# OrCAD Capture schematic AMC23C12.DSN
size A
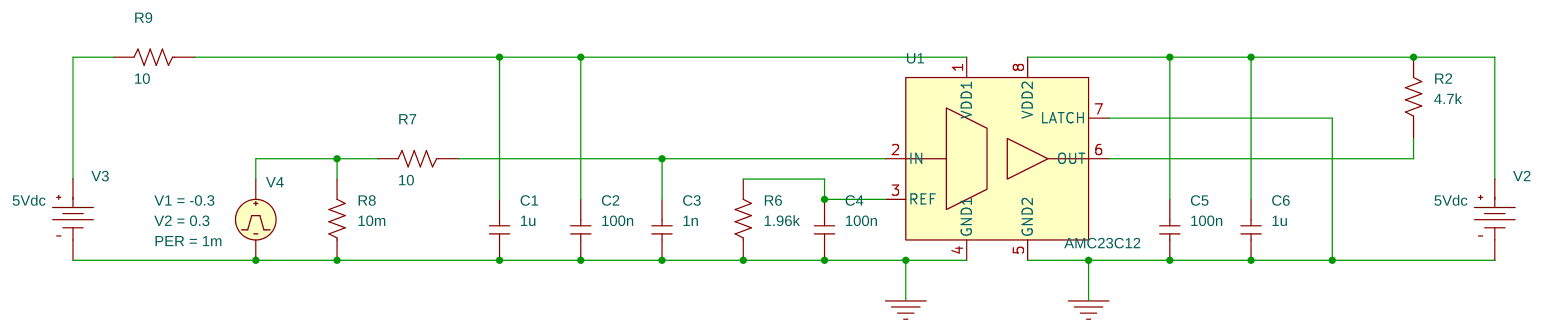
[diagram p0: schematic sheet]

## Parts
C1  1u  [cap196]
C2  100n  [cap196]
C3  1n  [cap196]
C4  100n  [cap196]
C5  100n  [cap196]
C6  1u  [cap196]
R2  4.7k  [AXRC05]
R6  1.96k  [AXRC05]
R7  10  [AXRC05]
R8  10m  [AXRC05]
R9  10  [AXRC05]
U1  AMC23C12
V2  VDC
V3  VDC
V4  VPULSE

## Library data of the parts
C1-C6 = C
R2 R6-R9 = R
U1 = AMC23C12
V2 V3 = VDC: DC: 5Vdc
V4 = VPULSE: AC: 0; AppProp: Pulse$Voltage$6$-1; DC: 0; PER: 1m; PW: 0; TD: 0; TF: 5.0000e-4; TR: 5.0000e-4; V1: -0.3; V2: 0.3

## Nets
0: C1.1 C2.1 C3.1 C4.1 C5.1 C6.1 R6.1 R8.1 U1.4(GND1) U1.5(GND2) U1.7(LATCH) V2.1(-) V3.1(-) V4.2(-)
N23450: C1.2 C2.2 R9.1 U1.1(VDD1)
N23454: C5.2 C6.2 R2.2 U1.8(VDD2) V2.0(+)
N23638: R2.1 U1.6(OUT)
N23678: C3.2 R7.1 U1.2(IN)
N23686: C4.2 R6.2 U1.3(REF)
N25908: R7.2 R8.2 V4.1(+)
N26290: R9.2 V3.0(+)
